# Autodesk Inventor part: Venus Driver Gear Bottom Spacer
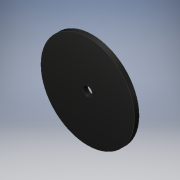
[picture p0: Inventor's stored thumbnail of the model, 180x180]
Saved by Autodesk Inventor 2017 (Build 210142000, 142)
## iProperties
Created: 2016-07
Part Number: Venus Driver Gear Bottom Spacer
Material: Generic
Document SubType Name: Modeling
Designer: Stan
Density: 1 g/cm^3
Appearance: Glossy - Black
Author: Stan
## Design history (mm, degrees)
sketch "Sketch1"
  geometry: C1 r 31.75 at (0, 0); C2 r 3.175 at (0, 0); 1 further point
  constraints: 2 centre point, 2 coincident
  dimensions: "d0" = 63.5 diameter of C1; "d1" = 6.35 diameter of C2
extrude "Extrusion1" new body sketch "Sketch1" distance "d2" = 3.175; taper "d3" = 0 deg
body "Solid1"
